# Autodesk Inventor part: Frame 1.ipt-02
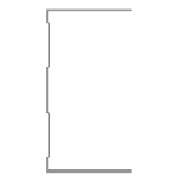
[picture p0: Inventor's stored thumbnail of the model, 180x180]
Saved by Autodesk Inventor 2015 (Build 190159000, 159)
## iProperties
IsCustomPart: 1
Created: 2015-04
Part Number: Frame 1.ipt-02
Material: Aluminum 6061
Description: Kévin Novo
Document SubType Name: Modeling
Standard: Kevin
Designer: suporte
Standards Organization: Kevin
Language: en-US
Size Designation: (Unnamed 2)
Categories: <MemberInstance><Categories><Category DisplayName="Structural Shapes" InternalName="089c4875-fa83-4c05-b084-43b9cc11f5ed" Mnemonic="GRDR"><CategoryParameter Dis
Density: 2.7 g/cm^3
Appearance: Aluminum - Flat
_CCFamilyMember: 2
_CCFamilyDisplayName: Kévin - Kévin Novo
_FrameMemberDoc: Frame Member File
_Version: 15.0.0
_GetPNFromCC: 1
G_W: 50,000 mm
G_H: 75,000 mm
G_L: 601,400 mm
+F5E5B542-A811-42A2-8BE7-F901652D0118+CUTDETAIL1: Cut
Author: suporte
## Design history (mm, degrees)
node "Start Plane"
node "End Plane"
sketch "Sketch"
  geometry: L1 (24.7, 37.5)-(24.7, 36.9); L2 (24.7, 36.9)-(-24.7, 36.9); L3 (-24.7, -36.9)-(24.7, -36.9); L4 (24.7, -36.9)-(24.7, -37.5); L5 (24.7, -37.5)-(-25.3, -37.5); L6 (-25.3, 37.5)-(24.7, 37.5); L7 (-24.7, 36.9)-(-24.7, 31.9); L8 (-24.7, 31.9)-(-23.3, 30.5); L9 (-23.3, 30.5)-(-23.3, 10.934); L10 (-23.3, 10.934)-(-24.7, 9.534); L11 (-24.7, 9.534)-(-24.7, -9.534); L12 (-24.7, -9.534)-(-23.3, -10.934); L13 (-23.3, -10.934)-(-23.3, -30.5); L14 (-23.3, -30.5)-(-24.7, -31.9); L15 (-24.7, -31.9)-(-24.7, -36.9); L16 (-25.3, -37.5)-(-25.3, -31.651); L17 (-25.3, -31.651)-(-23.9, -30.251); L18 (-23.9, -30.251)-(-23.9, -11.183); L19 (-23.9, -11.183)-(-25.3, -9.783); L20 (-25.3, -9.783)-(-25.3, 9.783); L21 (-25.3, 9.783)-(-23.9, 11.183); L22 (-23.9, 11.183)-(-23.9, 30.251); L23 (-23.9, 30.251)-(-25.3, 31.651); L24 (-25.3, 31.651)-(-25.3, 37.5); L25 (-25.3, 0)-(30.37, 0); 3 further points
  constraints: 50 end point, 10 point on line, 9 parallel, 5 perpendicular, 4 equal length, 3 midpoint, 3 vertical, 2 vertical alignment, 1 collinear, 1 horizontal, 1 horizontal alignment
  dimensions: "d3" = 0.6 distance of L1.start L1.end (= d6); "d5" = 75 distance between parallel lines of L5 L6; "d6" = 0.6 distance between parallel lines of L24 L7 (= d8); "d7" = 0.6 distance between parallel lines of L8 L23 (= d8); "d8" = 0.6 distance between parallel lines of L22 L9 (= d12); "Espessura" = 0.6 distance between parallel lines of L17 L14; "d10" = 0.6 distance between parallel lines of L13 L18 (= Espessura); "d11" = 0.6 distance between parallel lines of L12 L19 (= Espessura); "d12" = 0.6 distance between parallel lines of L21 L10 (= d11); "d13" = 5 distance of L2.end L7.end; "d15" = 135 deg angle of L9 L8; "d16" = 2 distance between parallel lines of L24 L9; "d17" = 50 distance of L6.start L1.start
extrude "Body" join sketch "Sketch" stored distance "d24" = 0.13; taper "d25" = 0 deg
node "Driven Length"
  sketch "Sketch10"
    geometry: L1 (0, 0)-(10, 0) reference
    constraints: 2 end point, 1 horizontal
  workplane "Work Plane7"
  sketch "Sketch11"
    geometry: L1 (-2, -1.4)-(12, -1.4) reference; L2 (-2, 600)-(12, 600) reference
    dimensions: "d27" = 601.4 distance between parallel lines of L1 L2 (derived)
workplane "Work Plane8"
split "Split1"
body "Solid1"
other parameters: "G_OFFSET_START" = 1.4 [user parameter; used in 1 equation term], "G_OFFSET_END" = 0 [user parameter; used in 1 equation term], "d22" = -1.4 (= -G_OFFSET_START), "G_L" = 601.4 (= d27) [user parameter], "d34" = 90 deg
